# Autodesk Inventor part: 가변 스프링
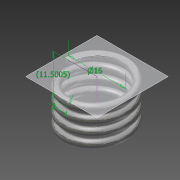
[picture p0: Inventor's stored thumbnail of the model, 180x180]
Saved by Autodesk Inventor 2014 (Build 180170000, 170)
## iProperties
Created: 2015-04
Part Number: 가변 스프링
Material: 강철, 탄소
Document SubType Name: Modeling
Designer: Administrator
Density: 7.87 g/cm^3
Appearance: 반연마
Mass: 4.77641 g
Surface Area: 12.5215 cm^2
Volume: 0.606913 cm^3
Author: Administrator
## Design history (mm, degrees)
sketch "스케치1"
  geometry: L1 (0, 0)-(-8, 0); L2 (-8, 0)-(-8, 11.5); L3 (-8, 11.5)-(0, 11.5); L4 (0, 11.5)-(0, 0); C1 r 1 at (-8, 0)
  constraints: 8 end point, 2 parallel, 1 centre point, 1 coincident, 1 horizontal, 1 perpendicular
  dimensions: "d0" = 16 diameter of L2 L4; "d1" = 11.50049 distance between parallel lines of L1 L3 (derived); "d2" = 2 diameter of C1
feature "코일1" pitch "d3" = 10; turns "d5" = 4; dims "d4" = 11.50049 (= d1), "d6" = 0, angle "d7" = 90 deg, angle "d8" = 90 deg, "d9" = 0, "d10" = 0
sketch "스케치2"
  geometry: L1 (9, 0)-(7, 0) reference; 1 further point
  constraints: 1 horizontal alignment
extrude "돌출1" cut sketch "스케치2" stored distance "d11" = 10; taper "d12" = 0 deg
node "작업 평면1"
sketch "스케치3"
  geometry: L1 (7, 0)-(9, 0) reference; 1 further point
  constraints: 1 horizontal alignment
extrude "돌출2" cut sketch "스케치3" stored distance "d13" = 10; taper "d14" = 0 deg
node "솔리드1"
node "절단 모서리 투영1"
node "절단 모서리 투영2"
